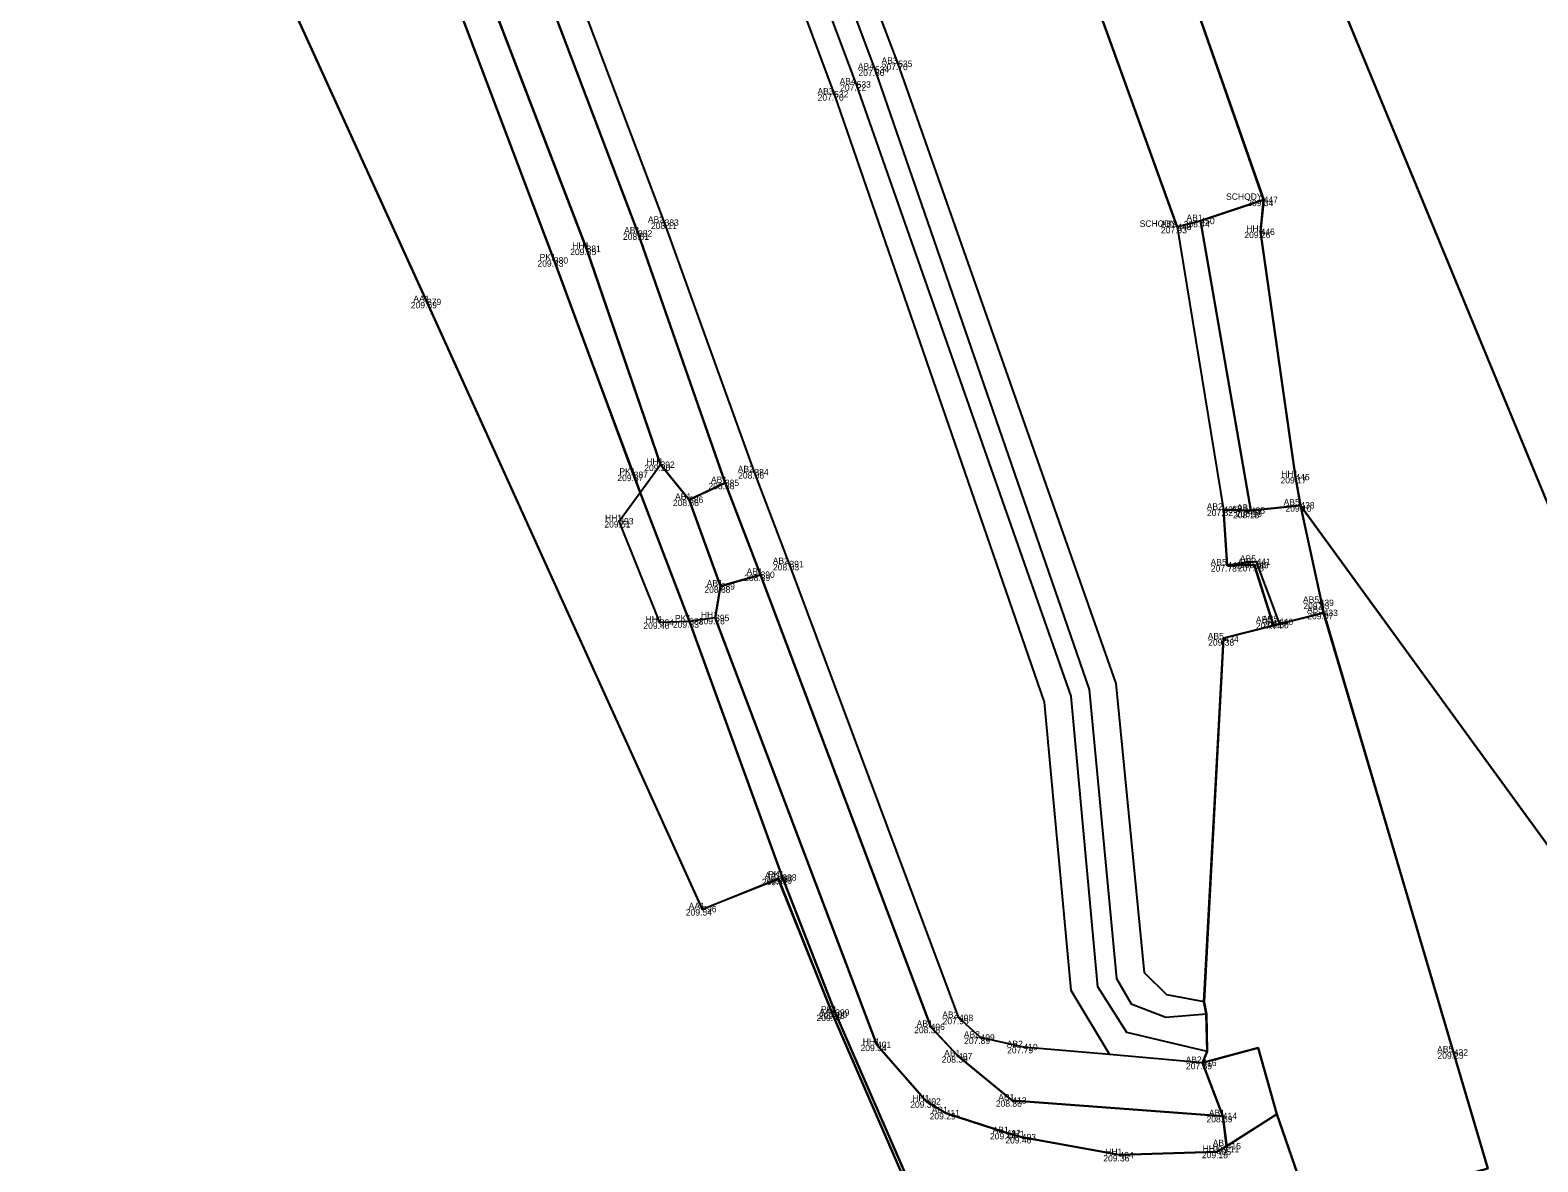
# Model space of a CAD drawing. Extents: x -262982 to -262706, y -1238714 to -1237093.
# Drawn here: x -262858.42 to -262811.08, y -1238695.45 to -1238659.92 of the extents above; entities that cross this region are included whole.
import ezdxf

# ---------------------------------------------------------------- set-up
doc = ezdxf.new("R2010")
doc.units = 0
for name, color, linetype in [('01_Hrana_betónu', 7, 'Continuous'), ('02_Oplotenie', 7, 'Continuous'), ('03_Asfalt', 7, 'Continuous'), ('05_Hrana_terénu', 7, 'Continuous'), ('06_Schody', 7, 'Continuous'), ('07_Iné', 7, 'Continuous'), ('08_Mimo_zelene', 7, 'Continuous'), ('Groma (21)', 7, 'Continuous'), ('Groma (22)', 7, 'Continuous'), ('Groma (23)', 7, 'Continuous'), ('Groma (24)', 7, 'Continuous'), ('U001_Betónové_panely', 7, 'Continuous'), ('U001_Betóny_prídavné', 7, 'Continuous'), ('U001_Ostatné_plochy', 7, 'Continuous'), ('U001_Schody', 7, 'Continuous'), ('U001_Zeleň_mimo', 7, 'Continuous'), ('U001_Zeleň_vnútro', 7, 'Continuous'), ('U001_Zeleň_zatrávňovač', 7, 'Continuous')]:
    doc.layers.add(name, color=color, linetype=linetype)

msp = doc.modelspace()

# ---------------------------------------------------------------- linework, layer by layer
at = {"layer": '01_Hrana_betónu'}
for p, q in [((-262822.4, -1238666.098), (-262820.949, -1238674.974)), ((-262820.09, -1238675.003), (-262821.671, -1238665.912))]:
    msp.add_line(p, q, dxfattribs=at)
for points in [[(-262945.09, -1238415.05), (-262943.108, -1238420.999), (-262942.065, -1238424.139), (-262934.754, -1238438.855), (-262923.683, -1238461.06), (-262913.753, -1238481.232), (-262903.896, -1238501.06), (-262894.759, -1238519.856), (-262890.317, -1238530.551), (-262883.158, -1238545.169), (-262873.572, -1238564.111), (-262869.728, -1238571.951), (-262860.562, -1238590.864), (-262854.835, -1238604.812), (-262840.38, -1238642.586), (-262833.174, -1238661.935), (-262826.575, -1238681.018), (-262825.738, -1238690.053), (-262824.527, -1238692.082)], [(-262821.464, -1238691.979), (-262823.978, -1238691.385), (-262824.893, -1238689.953), (-262825.729, -1238680.825), (-262832.468, -1238661.625), (-262839.672, -1238642.452), (-262854.271, -1238604.655), (-262859.863, -1238590.55), (-262868.949, -1238571.69), (-262872.864, -1238563.867), (-262882.403, -1238544.934), (-262889.591, -1238530.296), (-262894.035, -1238519.557), (-262903.102, -1238500.748), (-262912.912, -1238480.97), (-262922.987, -1238460.594), (-262933.962, -1238438.502), (-262941.314, -1238423.977), (-262942.296, -1238420.781), (-262943.962, -1238415.15)], [(-262941.142, -1238415.313), (-262941.461, -1238420.191), (-262940.383, -1238424.238), (-262933.343, -1238438.564), (-262922.27, -1238460.876), (-262912.449, -1238480.877), (-262902.557, -1238500.683), (-262893.416, -1238519.552), (-262889.058, -1238529.686), (-262881.962, -1238544.577), (-262872.106, -1238564.019), (-262868.478, -1238571.232), (-262859.211, -1238590.61), (-262852.998, -1238605.343), (-262846.933, -1238621.173), (-262838.559, -1238643.348), (-262831.894, -1238661.158), (-262825.164, -1238680.62), (-262824.312, -1238689.696), (-262823.847, -1238690.483), (-262822.763, -1238690.91), (-262821.486, -1238690.803)], [(-262821.555, -1238690.42), (-262822.731, -1238690.203), (-262823.426, -1238689.509), (-262824.318, -1238680.43), (-262831.163, -1238660.976), (-262837.946, -1238643.111), (-262846.365, -1238620.94), (-262852.333, -1238605.156), (-262858.618, -1238590.245), (-262867.784, -1238570.905), (-262871.416, -1238563.68), (-262881.223, -1238544.283), (-262888.392, -1238529.442), (-262892.626, -1238519.239), (-262901.725, -1238500.385), (-262911.6, -1238480.51), (-262921.479, -1238460.51), (-262932.607, -1238438.043), (-262939.752, -1238424.147), (-262940.771, -1238420.267), (-262940.559, -1238417.612), (-262940.205, -1238415.315)], [(-262821.612, -1238692.34), (-262824.527, -1238692.082), (-262827.229, -1238691.842), (-262828.578, -1238691.545), (-262829.254, -1238690.927), (-262834.577, -1238676.68), (-262835.677, -1238673.797), (-262838.498, -1238665.964), (-262846.729, -1238644.188), (-262854.634, -1238622.918), (-262863.262, -1238600.529), (-262868.088, -1238589.608)], [(-262868.934, -1238589.993), (-262864.101, -1238600.869), (-262855.602, -1238623.066), (-262847.622, -1238644.482), (-262839.332, -1238666.304), (-262836.604, -1238674.133), (-262835.486, -1238677.015), (-262830.144, -1238691.208), (-262829.282, -1238692.133), (-262827.58, -1238693.519), (-262820.969, -1238694.008)], [(-262820.949, -1238674.974), (-262820.828, -1238676.721), (-262819.978, -1238676.713), (-262819.376, -1238678.614), (-262820.948, -1238679.013), (-262821.555, -1238690.42)]]:
    msp.add_lwpolyline(points, dxfattribs=at)
at = {"layer": '02_Oplotenie'}
msp.add_lwpolyline([(-262896.033, -1238537.323), (-262884.611, -1238562.768), (-262875.332, -1238581.932), (-262871.26, -1238591.133), (-262867.507, -1238600.089), (-262859.113, -1238621.74), (-262850.323, -1238645.054), (-262841.974, -1238667.148), (-262839.469, -1238673.878), (-262839.26, -1238674.43), (-262837.725, -1238678.482), (-262834.801, -1238686.521), (-262833.14, -1238690.761), (-262828.35, -1238701.769), (-262822.156, -1238700.967), (-262816.462, -1238699.68), (-262807.77, -1238696.972), (-262807.339, -1238690.207)], dxfattribs=at)
at = {"layer": '03_Asfalt'}
msp.add_lwpolyline([(-262881.2, -1238585.494), (-262874.644, -1238603.324), (-262866.886, -1238624.256), (-262857.388, -1238650.091), (-262854.721, -1238649.057), (-262851.25, -1238656.85), (-262845.959, -1238668.452), (-262837.314, -1238687.515), (-262834.926, -1238686.561), (-262833.211, -1238690.828), (-262828.426, -1238701.842), (-262822.233, -1238701.015), (-262822.159, -1238701.403), (-262816.354, -1238699.919), (-262807.207, -1238697.538), (-262805.6, -1238694.487), (-262805.937, -1238690.489), (-262804.465, -1238690.033), (-262818.631, -1238655.736), (-262826.695, -1238636.389), (-262836.855, -1238611.872), (-262842.406, -1238598.306), (-262850.452, -1238578.707)], dxfattribs=at)
at = {"layer": '05_Hrana_terénu'}
for points in [[(-262820.846, -1238694.953), (-262821.157, -1238695.132), (-262824.214, -1238695.234), (-262827.282, -1238694.67), (-262827.759, -1238694.543), (-262829.668, -1238693.915), (-262830.272, -1238693.55), (-262831.828, -1238691.771), (-262836.912, -1238678.373), (-262837.725, -1238678.482), (-262838.648, -1238678.516), (-262839.921, -1238675.334), (-262839.26, -1238674.43), (-262838.626, -1238673.561), (-262840.949, -1238666.783), (-262849.249, -1238645.167), (-262857.406, -1238624.309), (-262870.41, -1238590.811)], [(-262819.685, -1238665.246), (-262819.785, -1238666.25), (-262818.688, -1238673.951), (-262818.534, -1238674.837)]]:
    msp.add_lwpolyline(points, dxfattribs=at)
at = {"layer": '06_Schody'}
msp.add_lwpolyline([(-262825.01, -1238658.867), (-262824.362, -1238658.568), (-262822.278, -1238657.844), (-262819.685, -1238665.246), (-262821.671, -1238665.912), (-262822.4, -1238666.098)], close=True, dxfattribs=at)
at = {"layer": '07_Iné'}
for points in [[(-262835.486, -1238677.015), (-262836.736, -1238677.384), (-262837.731, -1238674.662), (-262836.604, -1238674.133)], [(-262820.828, -1238676.721), (-262820.949, -1238674.974), (-262820.09, -1238675.003), (-262818.534, -1238674.837), (-262817.803, -1238678.214), (-262819.181, -1238678.564), (-262819.908, -1238676.609), (-262820.828, -1238676.721), (-262819.978, -1238676.713), (-262819.376, -1238678.614)], [(-262821.612, -1238692.34), (-262820.969, -1238694.008), (-262820.846, -1238694.953), (-262819.273, -1238693.95), (-262819.863, -1238691.866), (-262821.612, -1238692.34)]]:
    msp.add_lwpolyline(points, dxfattribs=at)
at = {"layer": '08_Mimo_zelene'}
msp.add_lwpolyline([(-262817.803, -1238678.214), (-262819.181, -1238678.564), (-262819.376, -1238678.614), (-262820.948, -1238679.013), (-262821.555, -1238690.42), (-262821.486, -1238690.803), (-262821.464, -1238691.979), (-262821.612, -1238692.34), (-262819.863, -1238691.866), (-262819.273, -1238693.95), (-262818.147, -1238697.183), (-262812.645, -1238695.656), (-262813.715, -1238692.011)], close=True, dxfattribs=at)
at = {"layer": 'Groma (21)'}
for centre in [(-262831.894, -1238661.158), (-262831.163, -1238660.976), (-262832.468, -1238661.625), (-262833.174, -1238661.935), (-262819.685, -1238665.246), (-262838.498, -1238665.964), (-262822.4, -1238666.098), (-262822.399, -1238666.095), (-262821.671, -1238665.912), (-262839.332, -1238666.304), (-262819.785, -1238666.25), (-262840.949, -1238666.783), (-262841.974, -1238667.148), (-262845.959, -1238668.452), (-262838.626, -1238673.561), (-262839.469, -1238673.878), (-262836.604, -1238674.133), (-262835.677, -1238673.797), (-262818.688, -1238673.951), (-262837.731, -1238674.662), (-262820.949, -1238674.974), (-262820.175, -1238675.043), (-262820.09, -1238675.003), (-262818.534, -1238674.837), (-262839.921, -1238675.334), (-262834.577, -1238676.68), (-262820.828, -1238676.721), (-262819.978, -1238676.713), (-262819.908, -1238676.609), (-262836.736, -1238677.384), (-262835.486, -1238677.015), (-262817.928, -1238677.897), (-262836.912, -1238678.373), (-262817.803, -1238678.214), (-262838.648, -1238678.516), (-262837.725, -1238678.482), (-262819.406, -1238678.523), (-262819.206, -1238678.497), (-262820.917, -1238679.042), (-262834.926, -1238686.561), (-262834.801, -1238686.521), (-262837.314, -1238687.515), (-262833.211, -1238690.828), (-262833.14, -1238690.761), (-262830.144, -1238691.208), (-262829.254, -1238690.927), (-262828.578, -1238691.545), (-262831.828, -1238691.771), (-262829.282, -1238692.133), (-262827.229, -1238691.842), (-262813.715, -1238692.011), (-262821.612, -1238692.34), (-262830.272, -1238693.55), (-262827.58, -1238693.519), (-262829.668, -1238693.915), (-262820.969, -1238694.008), (-262827.759, -1238694.543), (-262827.282, -1238694.67), (-262820.846, -1238694.953), (-262824.214, -1238695.234), (-262821.157, -1238695.132)]:
    msp.add_circle(centre, 0.01, dxfattribs=at)
at = {"layer": 'U001_Betónové_panely'}
msp.add_lwpolyline([(-262825.01, -1238658.87), (-262822.4, -1238666.1), (-262821.67, -1238665.91), (-262820.09, -1238675), (-262820.95, -1238674.97), (-262820.83, -1238676.72), (-262819.98, -1238676.71), (-262819.38, -1238678.61), (-262820.95, -1238679.01), (-262821.56, -1238690.42), (-262821.49, -1238690.8), (-262821.46, -1238691.98), (-262821.61, -1238692.34), (-262820.97, -1238694.01), (-262827.58, -1238693.52), (-262829.28, -1238692.13), (-262830.14, -1238691.21), (-262835.49, -1238677.02), (-262836.6, -1238674.13), (-262839.33, -1238666.3), (-262847.62, -1238644.48)], dxfattribs=at)
at = {"layer": 'U001_Betóny_prídavné'}
for points in [[(-262835.49, -1238677.02), (-262836.74, -1238677.38), (-262837.73, -1238674.66), (-262836.6, -1238674.13)], [(-262820.83, -1238676.72), (-262820.95, -1238674.97), (-262820.09, -1238675), (-262818.53, -1238674.84), (-262817.8, -1238678.21), (-262819.18, -1238678.56), (-262819.38, -1238678.61), (-262819.98, -1238676.71)], [(-262819.27, -1238693.95), (-262820.85, -1238694.95), (-262820.97, -1238694.01), (-262821.61, -1238692.34), (-262819.86, -1238691.87)]]:
    msp.add_lwpolyline(points, close=True, dxfattribs=at)
at = {"layer": 'U001_Ostatné_plochy'}
msp.add_lwpolyline([(-262818.15, -1238697.18), (-262819.27, -1238693.95), (-262819.86, -1238691.87), (-262821.61, -1238692.34), (-262821.46, -1238691.98), (-262821.49, -1238690.8), (-262821.56, -1238690.42), (-262820.95, -1238679.01), (-262819.38, -1238678.61), (-262819.18, -1238678.56), (-262817.8, -1238678.21), (-262813.72, -1238692.01), (-262812.65, -1238695.66)], close=True, dxfattribs=at)
at = {"layer": 'U001_Schody'}
msp.add_lwpolyline([(-262824.36, -1238658.57), (-262822.28, -1238657.84), (-262819.69, -1238665.25), (-262821.67, -1238665.91), (-262822.4, -1238666.1), (-262825.01, -1238658.87)], close=True, dxfattribs=at)
at = {"layer": 'U001_Zeleň_mimo'}
for points in [[(-262850.45, -1238578.71), (-262842.41, -1238598.31), (-262836.86, -1238611.87), (-262826.7, -1238636.39), (-262818.63, -1238655.74), (-262804.47, -1238690.03), (-262805.94, -1238690.49), (-262805.6, -1238694.49), (-262807.21, -1238697.54), (-262816.35, -1238699.92), (-262822.16, -1238701.4), (-262822.23, -1238701.02), (-262828.43, -1238701.84), (-262833.21, -1238690.83), (-262834.93, -1238686.56), (-262837.31, -1238687.52), (-262845.96, -1238668.45), (-262851.25, -1238656.85), (-262854.72, -1238649.06), (-262857.39, -1238650.09), (-262866.89, -1238624.26), (-262874.64, -1238603.32), (-262881.2, -1238585.49)], [(-262850.45, -1238578.71), (-262842.41, -1238598.31), (-262836.86, -1238611.87), (-262826.7, -1238636.39), (-262818.63, -1238655.74), (-262804.47, -1238690.03), (-262805.94, -1238690.49), (-262805.6, -1238694.49), (-262807.21, -1238697.54), (-262816.35, -1238699.92), (-262822.16, -1238701.4), (-262822.23, -1238701.02), (-262828.43, -1238701.84), (-262833.21, -1238690.83), (-262834.93, -1238686.56), (-262837.31, -1238687.52), (-262845.96, -1238668.45), (-262851.25, -1238656.85), (-262854.72, -1238649.06), (-262857.39, -1238650.09), (-262866.89, -1238624.26), (-262874.64, -1238603.32), (-262881.2, -1238585.49)], [(-262850.32, -1238645.05), (-262841.97, -1238667.15), (-262839.47, -1238673.88), (-262839.26, -1238674.43), (-262837.72, -1238678.48), (-262834.8, -1238686.52), (-262833.14, -1238690.76), (-262828.35, -1238701.77), (-262822.16, -1238700.97), (-262816.46, -1238699.68), (-262807.77, -1238696.97), (-262807.34, -1238690.21), (-262818.53, -1238674.84), (-262818.69, -1238673.95), (-262819.78, -1238666.25), (-262819.69, -1238665.25), (-262822.28, -1238657.84)]]:
    msp.add_lwpolyline(points, dxfattribs=at)
at = {"layer": 'U001_Zeleň_vnútro'}
for points in [[(-262807.77, -1238696.97), (-262816.46, -1238699.68), (-262822.16, -1238700.97), (-262828.35, -1238701.77), (-262833.14, -1238690.76), (-262834.8, -1238686.52), (-262837.72, -1238678.48), (-262839.26, -1238674.43), (-262839.47, -1238673.88), (-262841.97, -1238667.15), (-262850.32, -1238645.05)], [(-262849.25, -1238645.17), (-262840.95, -1238666.78), (-262838.63, -1238673.56), (-262837.73, -1238674.66), (-262836.74, -1238677.38), (-262836.91, -1238678.37), (-262831.83, -1238691.77), (-262830.27, -1238693.55), (-262829.67, -1238693.92), (-262827.76, -1238694.54), (-262827.28, -1238694.67), (-262824.21, -1238695.23), (-262821.16, -1238695.13), (-262820.85, -1238694.95), (-262819.27, -1238693.95), (-262818.15, -1238697.18), (-262812.65, -1238695.66), (-262813.72, -1238692.01), (-262817.8, -1238678.21), (-262818.53, -1238674.84), (-262807.34, -1238690.21)]]:
    msp.add_lwpolyline(points, dxfattribs=at)
at = {"layer": 'U001_Zeleň_zatrávňovač'}
msp.add_lwpolyline([(-262868.93, -1238589.99), (-262864.1, -1238600.87), (-262855.6, -1238623.07), (-262847.62, -1238644.48), (-262839.33, -1238666.3), (-262836.6, -1238674.13), (-262837.73, -1238674.66), (-262838.63, -1238673.56), (-262840.95, -1238666.78), (-262849.25, -1238645.17), (-262857.41, -1238624.31), (-262870.41, -1238590.81)], dxfattribs=at)
for points in [[(-262819.78, -1238666.25), (-262818.69, -1238673.95), (-262818.53, -1238674.84), (-262820.09, -1238675), (-262821.67, -1238665.91), (-262819.69, -1238665.25)], [(-262836.91, -1238678.37), (-262836.74, -1238677.38), (-262835.49, -1238677.02), (-262830.14, -1238691.21), (-262829.28, -1238692.13), (-262827.58, -1238693.52), (-262820.97, -1238694.01), (-262820.85, -1238694.95), (-262821.16, -1238695.13), (-262824.21, -1238695.23), (-262827.28, -1238694.67), (-262827.76, -1238694.54), (-262829.67, -1238693.92), (-262830.27, -1238693.55), (-262831.83, -1238691.77)]]:
    msp.add_lwpolyline(points, close=True, dxfattribs=at)

# ---------------------------------------------------------------- texts
at = {"layer": 'Groma (22)'}
for s, p in [('535', (-262831.163, -1238661.076)), ('534', (-262831.894, -1238661.258)), ('532', (-262833.174, -1238662.035)), ('533', (-262832.468, -1238661.725)), ('447', (-262819.685, -1238665.346)), ('383', (-262838.498, -1238666.064)), ('449', (-262822.4, -1238666.198)), ('448', (-262822.399, -1238666.195)), ('450', (-262821.671, -1238666.012)), ('382', (-262839.332, -1238666.404)), ('446', (-262819.785, -1238666.35)), ('380', (-262841.974, -1238667.248)), ('381', (-262840.949, -1238666.883)), ('379', (-262845.959, -1238668.552)), ('392', (-262838.626, -1238673.661)), ('387', (-262839.469, -1238673.978)), ('385', (-262836.604, -1238674.233)), ('384', (-262835.677, -1238673.897)), ('445', (-262818.688, -1238674.051)), ('386', (-262837.731, -1238674.762)), ('436', (-262820.949, -1238675.074)), ('437', (-262820.175, -1238675.143)), ('435', (-262820.09, -1238675.103)), ('438', (-262818.534, -1238674.937)), ('393', (-262839.921, -1238675.434)), ('441', (-262819.908, -1238676.709)), ('390', (-262835.486, -1238677.115)), ('391', (-262834.577, -1238676.78)), ('442', (-262820.828, -1238676.821)), ('443', (-262819.978, -1238676.813)), ('389', (-262836.736, -1238677.484)), ('439', (-262817.928, -1238677.997)), ('394', (-262838.648, -1238678.616)), ('388', (-262837.725, -1238678.582)), ('395', (-262836.912, -1238678.473)), ('440', (-262819.206, -1238678.597)), ('433', (-262817.803, -1238678.314)), ('444', (-262819.406, -1238678.623)), ('434', (-262820.917, -1238679.142)), ('397', (-262834.926, -1238686.661)), ('398', (-262834.801, -1238686.621)), ('396', (-262837.314, -1238687.615)), ('400', (-262833.211, -1238690.928)), ('399', (-262833.14, -1238690.861)), ('406', (-262830.144, -1238691.308)), ('408', (-262829.254, -1238691.027)), ('401', (-262831.828, -1238691.871)), ('409', (-262828.578, -1238691.645)), ('407', (-262829.282, -1238692.233)), ('410', (-262827.229, -1238691.942)), ('432', (-262813.715, -1238692.111)), ('416', (-262821.612, -1238692.44)), ('402', (-262830.272, -1238693.65)), ('413', (-262827.58, -1238693.619)), ('411', (-262829.668, -1238694.015)), ('414', (-262820.969, -1238694.108)), ('412', (-262827.759, -1238694.643)), ('403', (-262827.282, -1238694.77)), ('415', (-262820.846, -1238695.053)), ('404', (-262824.214, -1238695.334)), ('405', (-262821.157, -1238695.232))]:
    msp.add_text(s, height=0.2, dxfattribs=at).set_placement(p)
at = {"layer": 'Groma (23)'}
for s, p in [('207.30', (-262832.411, -1238661.358)), ('207.70', (-262831.68, -1238661.176)), ('207.22', (-262832.985, -1238661.825)), ('207.70', (-262833.691, -1238662.135)), ('209.34', (-262820.202, -1238665.446)), ('208.11', (-262838.928, -1238666.164)), ('207.93', (-262822.913, -1238666.298)), ('207.93', (-262822.912, -1238666.295)), ('208.44', (-262822.197, -1238666.112)), ('208.51', (-262839.805, -1238666.504)), ('209.26', (-262820.292, -1238666.45)), ('209.35', (-262841.461, -1238666.983)), ('209.43', (-262842.491, -1238667.348)), ('209.59', (-262846.466, -1238668.652)), ('209.20', (-262839.137, -1238673.761)), ('209.37', (-262839.982, -1238674.078)), ('208.38', (-262837.121, -1238674.333)), ('208.06', (-262836.188, -1238673.997)), ('209.17', (-262819.157, -1238674.151)), ('208.66', (-262838.238, -1238674.862)), ('207.82', (-262821.466, -1238675.174)), ('208.18', (-262820.648, -1238675.243)), ('208.16', (-262820.558, -1238675.203)), ('209.10', (-262819.002, -1238675.037)), ('209.51', (-262840.389, -1238675.534)), ('208.03', (-262835.093, -1238676.88)), ('207.78', (-262821.346, -1238676.921)), ('207.78', (-262820.496, -1238676.913)), ('208.58', (-262820.425, -1238676.809)), ('208.68', (-262837.248, -1238677.584)), ('208.39', (-262835.998, -1238677.215)), ('209.03', (-262818.439, -1238678.097)), ('209.28', (-262837.424, -1238678.573)), ('209.07', (-262818.315, -1238678.414)), ('209.40', (-262839.164, -1238678.716)), ('209.33', (-262838.237, -1238678.682)), ('207.74', (-262819.929, -1238678.723)), ('208.60', (-262819.717, -1238678.697)), ('209.38', (-262821.429, -1238679.242)), ('209.42', (-262835.443, -1238686.761)), ('209.40', (-262835.317, -1238686.721)), ('209.54', (-262837.831, -1238687.715)), ('209.47', (-262833.728, -1238691.028)), ('209.48', (-262833.657, -1238690.961)), ('207.95', (-262829.767, -1238691.127)), ('208.38', (-262830.661, -1238691.408)), ('207.89', (-262829.091, -1238691.745)), ('209.34', (-262832.345, -1238691.971)), ('208.39', (-262829.794, -1238692.333)), ('207.79', (-262827.742, -1238692.042)), ('209.25', (-262814.227, -1238692.211)), ('207.59', (-262822.125, -1238692.54)), ('209.33', (-262830.784, -1238693.75)), ('208.80', (-262828.096, -1238693.719)), ('209.29', (-262830.175, -1238694.115)), ('208.59', (-262821.481, -1238694.208)), ('209.44', (-262828.28, -1238694.743)), ('209.40', (-262827.798, -1238694.87)), ('209.11', (-262821.271, -1238695.153)), ('209.36', (-262824.721, -1238695.434)), ('209.18', (-262821.625, -1238695.332))]:
    msp.add_text(s, height=0.2, dxfattribs=at).set_placement(p)
at = {"layer": 'Groma (24)'}
for s, p in [('AB3', (-262831.687, -1238660.976)), ('AB4', (-262832.428, -1238661.158)), ('AB3', (-262833.698, -1238661.935)), ('AB4', (-262833.002, -1238661.625)), ('SCHODY', (-262820.866, -1238665.246)), ('AB1', (-262839.77, -1238666.304)), ('AB2', (-262839.022, -1238665.964)), ('SCHODY', (-262823.58, -1238666.095)), ('AB2', (-262822.924, -1238666.098)), ('AB1', (-262822.109, -1238665.912)), ('HH1', (-262820.232, -1238666.25)), ('HH1', (-262841.396, -1238666.783)), ('PK1', (-262842.421, -1238667.148)), ('AA1', (-262846.387, -1238668.452)), ('PK1', (-262839.916, -1238673.878)), ('HH1', (-262839.073, -1238673.561)), ('AB2', (-262836.201, -1238673.797)), ('AB1', (-262837.042, -1238674.133)), ('HH1', (-262819.135, -1238673.951)), ('AB1', (-262838.169, -1238674.662)), ('AB2', (-262821.473, -1238674.974)), ('AB5', (-262820.699, -1238675.043)), ('AB1', (-262820.528, -1238675.003)), ('AB5', (-262819.058, -1238674.837)), ('HH1', (-262840.368, -1238675.334)), ('AB2', (-262835.101, -1238676.68)), ('AB5', (-262821.352, -1238676.721)), ('AB5', (-262820.502, -1238676.713)), ('AB5', (-262820.432, -1238676.609)), ('AB1', (-262835.924, -1238677.015)), ('AB1', (-262837.174, -1238677.384)), ('AB5', (-262818.452, -1238677.897)), ('HH1', (-262839.095, -1238678.516)), ('PK1', (-262838.172, -1238678.482)), ('HH1', (-262837.359, -1238678.373)), ('AB5', (-262819.93, -1238678.523)), ('AB5', (-262819.73, -1238678.497)), ('AB5', (-262818.327, -1238678.214)), ('AB5', (-262821.441, -1238679.042)), ('AA1', (-262835.354, -1238686.561)), ('PK1', (-262835.248, -1238686.521)), ('AA1', (-262837.742, -1238687.515)), ('AA1', (-262833.639, -1238690.828)), ('PK1', (-262833.587, -1238690.761)), ('AB2', (-262829.778, -1238690.927)), ('AB1', (-262830.582, -1238691.208)), ('HH1', (-262832.275, -1238691.771)), ('AB2', (-262829.102, -1238691.545)), ('AB2', (-262827.753, -1238691.842)), ('AB1', (-262829.72, -1238692.133)), ('AB2', (-262822.136, -1238692.34)), ('AB5', (-262814.239, -1238692.011)), ('HH1', (-262830.719, -1238693.55)), ('AB1', (-262828.018, -1238693.519)), ('AB1', (-262830.106, -1238693.915)), ('AB1', (-262821.407, -1238694.008)), ('AB1', (-262828.197, -1238694.543)), ('HH1', (-262827.729, -1238694.67)), ('HH1', (-262821.604, -1238695.132)), ('AB1', (-262821.284, -1238694.953)), ('HH1', (-262824.661, -1238695.234))]:
    msp.add_text(s, height=0.2, dxfattribs=at).set_placement(p)

doc.saveas('drawing.dxf')
